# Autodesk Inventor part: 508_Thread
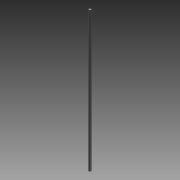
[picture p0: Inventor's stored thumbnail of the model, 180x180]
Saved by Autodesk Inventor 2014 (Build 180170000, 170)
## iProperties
Created: 2013-12
Part Number: 508_Thread
Material: Stainless Steel
Document SubType Name: Modeling
Designer: Bram
Density: 8.08 g/cm^3
Appearance: Semi-Polished
Author: Bram
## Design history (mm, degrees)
sketch "Sketch1"
  geometry: C1 r 4 at (0, 0); 1 further point
  constraints: 1 centre point, 1 coincident
  dimensions: "d0" = 8 diameter of C1
extrude "Extrusion1" new body sketch "Sketch1" distance "d1" = 508; taper "d2" = 0 deg
thread "Thread1" dims "d3" = 10, "d4" = 0
body "Solid1"
